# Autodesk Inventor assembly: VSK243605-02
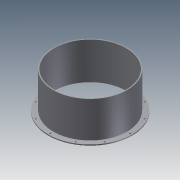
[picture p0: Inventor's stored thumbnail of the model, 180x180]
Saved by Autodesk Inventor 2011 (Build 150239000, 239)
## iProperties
Created: 2010-06
Part Number: VSK243605-02
Document SubType Name: Assembly
Designer: mklassen
OD: 36.000 in
THK: 0.500 in
SKVOFS: -6.000 in
SKLEN: 3.500 ft
Author: mklassen
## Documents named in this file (3)
- O:\cadd\tutorials\inventor 2011\iLogic\VSK243605-02.iam
- O:\cadd\tutorials\inventor 2011\iLogic\Skirt-01-03.ipt
- O:\cadd\tutorials\inventor 2011\iLogic\SkirtFlange-01-03.ipt
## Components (2 placed, 2 different names)
1. Skirt-01:1 — Flush:1, Flush:2, Flush:3
2. SkirtFlange-01:1 — Flush:4, Flush:5
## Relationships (5: Flush 5)
- Flush:1: Skirt-01:1
- Flush:2: Skirt-01:1
- Flush:3: Skirt-01:1
- Flush:4: SkirtFlange-01:1
- Flush:5: SkirtFlange-01:1
